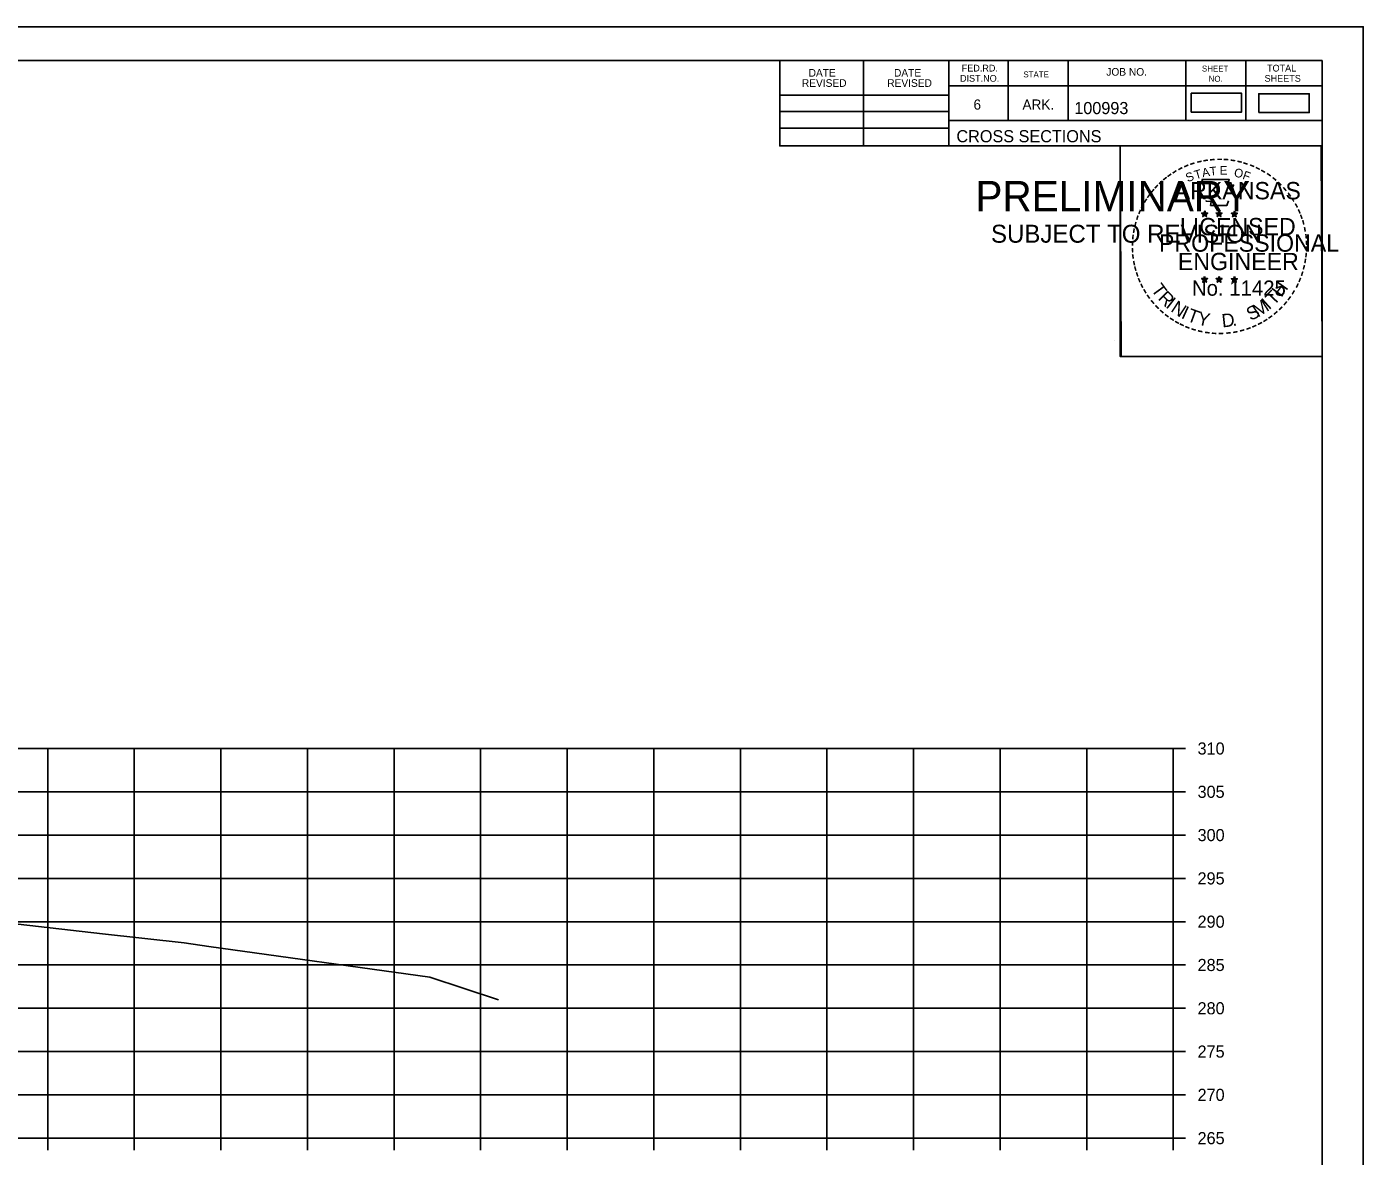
# Model space of a CAD drawing. Extents: x 4667 to 1632277, y -2100 to 724501.
# Drawn here: x 5814.8 to 5969.1, y 1319.2 to 1449.6 of the extents above; entities that cross this region are included whole.
import ezdxf

# ---------------------------------------------------------------- set-up
doc = ezdxf.new("R2010")
doc.units = 0
for name, color, linetype in [('Default', 7, 'Continuous'), ('R_Axis', 7, 'Continuous'), ('R_Axis Annot', 7, 'Continuous'), ('R_Border', 7, 'Continuous'), ('R_Border PE', 7, 'Continuous'), ('R_Border Prem', 7, 'Continuous'), ('R_Exist Surface', 7, 'Continuous'), ('R_Grid', 7, 'Continuous'), ('R_No Plot', 7, 'Continuous')]:
    doc.layers.add(name, color=color, linetype=linetype)

msp = doc.modelspace()

# ---------------------------------------------------------------- linework, layer by layer
at = {"layer": 'Default'}
for points in [[(5949.24, 1439.78), (5955.07, 1439.78), (5955.07, 1441.97), (5949.24, 1441.97)], [(5957.04, 1439.72), (5962.87, 1439.72), (5962.87, 1441.91), (5957.04, 1441.91)]]:
    msp.add_lwpolyline(points, close=True, dxfattribs=at)
at = {"layer": 'R_Axis'}
for p, q in [((5947.18, 1321.29), (5947.18, 1366.29)), ((5948.58, 1366.29), (5947.18, 1366.29)), ((5948.58, 1361.29), (5947.18, 1361.29)), ((5948.58, 1356.29), (5947.18, 1356.29)), ((5948.58, 1351.29), (5947.18, 1351.29)), ((5948.58, 1346.29), (5947.18, 1346.29)), ((5948.58, 1341.29), (5947.18, 1341.29)), ((5948.58, 1336.29), (5947.18, 1336.29)), ((5948.58, 1331.29), (5947.18, 1331.29)), ((5948.58, 1326.29), (5947.18, 1326.29)), ((5667.18, 1321.29), (5947.18, 1321.29)), ((5817.18, 1319.89), (5817.18, 1321.29)), ((5827.18, 1319.89), (5827.18, 1321.29)), ((5837.18, 1319.89), (5837.18, 1321.29)), ((5847.18, 1319.89), (5847.18, 1321.29)), ((5857.18, 1319.89), (5857.18, 1321.29)), ((5867.18, 1319.89), (5867.18, 1321.29)), ((5877.18, 1319.89), (5877.18, 1321.29)), ((5887.18, 1319.89), (5887.18, 1321.29)), ((5897.18, 1319.89), (5897.18, 1321.29)), ((5907.18, 1319.89), (5907.18, 1321.29)), ((5917.18, 1319.89), (5917.18, 1321.29)), ((5927.18, 1319.89), (5927.18, 1321.29)), ((5937.18, 1319.89), (5937.18, 1321.29)), ((5947.18, 1319.89), (5947.18, 1321.29)), ((5948.58, 1321.29), (5947.18, 1321.29))]:
    msp.add_line(p, q, dxfattribs=at)
at = {"layer": 'R_Border'}
for p, q in [((5648.18, 1445.75), (5964.36, 1445.75)), ((5901.72, 1435.87), (5901.72, 1445.75)), ((5911.4, 1435.87), (5911.4, 1445.75)), ((5921.26, 1445.75), (5921.26, 1435.87)), ((5928.1, 1445.75), (5928.1, 1438.81)), ((5935.04, 1445.75), (5935.04, 1438.81)), ((5948.62, 1445.75), (5948.62, 1438.81)), ((5955.56, 1445.75), (5955.56, 1438.81)), ((5964.36, 1240.29), (5964.36, 1445.75)), ((5964.36, 1442.81), (5921.26, 1442.81)), ((5964.36, 1442.83), (5964.36, 1442.83)), ((5901.72, 1441.73), (5921.26, 1441.73)), ((5901.72, 1439.87), (5921.26, 1439.87)), ((5964.36, 1438.81), (5921.26, 1438.81)), ((5924.22, 1438.81), (5964.36, 1438.81)), ((5901.72, 1437.93), (5921.26, 1437.93)), ((5964.36, 1435.87), (5901.72, 1435.87))]:
    msp.add_line(p, q, dxfattribs=at)
at = {"layer": 'R_Border PE'}
for p, q in [((5950.45, 1428.12), (5950.8, 1428.01)), ((5950.45, 1428.12), (5950.7, 1428.08)), ((5950.45, 1428.12), (5950.69, 1428)), ((5950.58, 1427.71), (5950.8, 1428.01)), ((5950.58, 1427.71), (5950.71, 1427.96)), ((5950.58, 1427.71), (5950.8, 1427.93)), ((5950.8, 1428.38), (5950.76, 1428.12)), ((5950.8, 1428.01), (5950.8, 1428.38)), ((5950.8, 1428.38), (5950.85, 1428.13)), ((5951.15, 1428.12), (5950.8, 1428.01)), ((5951.01, 1427.71), (5950.8, 1428.01)), ((5951.01, 1427.71), (5950.8, 1427.93)), ((5951.15, 1428.12), (5950.86, 1428.07)), ((5951.01, 1427.71), (5950.87, 1428.01)), ((5951.15, 1428.12), (5950.94, 1428.02)), ((5952.12, 1428.12), (5952.47, 1428.01)), ((5952.12, 1428.12), (5952.37, 1428.08)), ((5952.12, 1428.12), (5952.36, 1428)), ((5952.25, 1427.71), (5952.47, 1428.01)), ((5952.25, 1427.71), (5952.38, 1427.96)), ((5952.25, 1427.71), (5952.47, 1427.93)), ((5952.47, 1428.38), (5952.43, 1428.12)), ((5952.47, 1428.01), (5952.47, 1428.38)), ((5952.47, 1428.38), (5952.52, 1428.13)), ((5952.82, 1428.12), (5952.47, 1428.01)), ((5952.68, 1427.71), (5952.47, 1428.01)), ((5952.68, 1427.71), (5952.47, 1427.93)), ((5952.82, 1428.12), (5952.53, 1428.07)), ((5952.68, 1427.71), (5952.54, 1428.01)), ((5952.82, 1428.12), (5952.61, 1428.02)), ((5953.88, 1428.11), (5954.23, 1428)), ((5953.88, 1428.11), (5954.14, 1428.07)), ((5953.88, 1428.11), (5954.12, 1427.99)), ((5954.02, 1427.7), (5954.23, 1428)), ((5954.02, 1427.7), (5954.14, 1427.95)), ((5954.02, 1427.7), (5954.23, 1427.92)), ((5954.23, 1428.36), (5954.19, 1428.11)), ((5954.23, 1428), (5954.23, 1428.36)), ((5954.23, 1428.36), (5954.28, 1428.11)), ((5954.58, 1428.11), (5954.23, 1428)), ((5954.45, 1427.7), (5954.23, 1428)), ((5954.45, 1427.7), (5954.23, 1427.92)), ((5954.58, 1428.11), (5954.29, 1428.06)), ((5954.45, 1427.7), (5954.31, 1427.99)), ((5954.58, 1428.11), (5954.38, 1428.01)), ((5950.45, 1420.55), (5950.79, 1420.44)), ((5950.45, 1420.55), (5950.7, 1420.5)), ((5950.45, 1420.55), (5950.68, 1420.43)), ((5950.58, 1420.14), (5950.79, 1420.44)), ((5950.58, 1420.14), (5950.7, 1420.39)), ((5950.58, 1420.14), (5950.79, 1420.36)), ((5950.79, 1420.8), (5950.75, 1420.55)), ((5950.79, 1420.44), (5950.79, 1420.8)), ((5950.79, 1420.8), (5950.84, 1420.55)), ((5951.14, 1420.55), (5950.79, 1420.44)), ((5951.01, 1420.14), (5950.79, 1420.44)), ((5951.01, 1420.14), (5950.79, 1420.36)), ((5951.14, 1420.55), (5950.86, 1420.5)), ((5951.01, 1420.14), (5950.87, 1420.43)), ((5951.14, 1420.55), (5950.94, 1420.45)), ((5952.11, 1420.55), (5952.46, 1420.44)), ((5952.11, 1420.55), (5952.37, 1420.5)), ((5952.11, 1420.55), (5952.35, 1420.43)), ((5952.25, 1420.14), (5952.46, 1420.44)), ((5952.25, 1420.14), (5952.37, 1420.39)), ((5952.25, 1420.14), (5952.46, 1420.36)), ((5952.46, 1420.8), (5952.42, 1420.55)), ((5952.46, 1420.44), (5952.46, 1420.8)), ((5952.46, 1420.8), (5952.51, 1420.55)), ((5952.81, 1420.55), (5952.46, 1420.44)), ((5952.68, 1420.14), (5952.46, 1420.44)), ((5952.68, 1420.14), (5952.46, 1420.36)), ((5952.81, 1420.55), (5952.52, 1420.5)), ((5952.68, 1420.14), (5952.54, 1420.43)), ((5952.81, 1420.55), (5952.61, 1420.45)), ((5953.88, 1420.54), (5954.23, 1420.43)), ((5953.88, 1420.54), (5954.13, 1420.49)), ((5953.88, 1420.54), (5954.12, 1420.42)), ((5954.01, 1420.13), (5954.23, 1420.43)), ((5954.01, 1420.13), (5954.14, 1420.38)), ((5954.01, 1420.13), (5954.23, 1420.35)), ((5954.23, 1420.79), (5954.19, 1420.54)), ((5954.23, 1420.43), (5954.23, 1420.79)), ((5954.23, 1420.79), (5954.28, 1420.54)), ((5954.58, 1420.54), (5954.23, 1420.43)), ((5954.44, 1420.13), (5954.23, 1420.43)), ((5954.44, 1420.13), (5954.23, 1420.35)), ((5954.58, 1420.54), (5954.29, 1420.49)), ((5954.44, 1420.13), (5954.31, 1420.42)), ((5954.58, 1420.54), (5954.37, 1420.44))]:
    msp.add_line(p, q, dxfattribs=at)
for points in [[(5950.49, 1432), (5950.76, 1431.17)], [(5954, 1431.08), (5954.14, 1431.36), (5953.46, 1431.34), (5953.61, 1432), (5950.49, 1432)], [(5950.98, 1429.58), (5950.98, 1429.49), (5951.55, 1429.47), (5951.49, 1429), (5953.36, 1429), (5953.56, 1429.53)], [(5950.8, 1428.38), (5951.01, 1427.71), (5950.45, 1428.12), (5951.15, 1428.12), (5950.58, 1427.71), (5950.8, 1428.38)], [(5952.47, 1428.38), (5952.68, 1427.71), (5952.12, 1428.12), (5952.82, 1428.12), (5952.25, 1427.71), (5952.47, 1428.38)], [(5954.23, 1428.36), (5954.45, 1427.7), (5953.88, 1428.11), (5954.58, 1428.11), (5954.02, 1427.7), (5954.23, 1428.36)], [(5950.79, 1420.8), (5951.01, 1420.14), (5950.45, 1420.55), (5951.14, 1420.55), (5950.58, 1420.14), (5950.79, 1420.8)], [(5952.46, 1420.8), (5952.68, 1420.14), (5952.11, 1420.55), (5952.81, 1420.55), (5952.25, 1420.14), (5952.46, 1420.8)], [(5954.23, 1420.79), (5954.44, 1420.13), (5953.88, 1420.54), (5954.58, 1420.54), (5954.01, 1420.13), (5954.23, 1420.79)]]:
    msp.add_lwpolyline(points, dxfattribs=at)
for centre, radius in [((5950.8, 1428.01), 0.172), ((5950.8, 1428.01), 0.145), ((5950.8, 1428.01), 0.116), ((5950.8, 1428.01), 0.0991), ((5950.8, 1428.01), 0.0747), ((5950.8, 1428.01), 0.0495), ((5950.8, 1428.01), 0.0296), ((5952.47, 1428.01), 0.172), ((5952.47, 1428.01), 0.145), ((5952.47, 1428.01), 0.116), ((5952.47, 1428.01), 0.0991), ((5952.47, 1428.01), 0.0747), ((5952.47, 1428.01), 0.0495), ((5952.47, 1428.01), 0.0296), ((5954.23, 1428), 0.172), ((5954.23, 1428), 0.145), ((5954.23, 1428), 0.116), ((5954.23, 1428), 0.0991), ((5954.23, 1428), 0.0747), ((5954.23, 1428), 0.0495), ((5954.23, 1428), 0.0296), ((5950.79, 1420.44), 0.172), ((5950.79, 1420.44), 0.145), ((5950.79, 1420.44), 0.116), ((5950.79, 1420.44), 0.0991), ((5950.79, 1420.44), 0.0747), ((5950.79, 1420.44), 0.0495), ((5950.79, 1420.44), 0.0296), ((5952.46, 1420.44), 0.172), ((5952.46, 1420.44), 0.145), ((5952.46, 1420.44), 0.116), ((5952.46, 1420.44), 0.0991), ((5952.46, 1420.44), 0.0747), ((5952.46, 1420.44), 0.0495), ((5952.46, 1420.44), 0.0296), ((5954.23, 1420.43), 0.172), ((5954.23, 1420.43), 0.145), ((5954.23, 1420.43), 0.116), ((5954.23, 1420.43), 0.0991), ((5954.23, 1420.43), 0.0747), ((5954.23, 1420.43), 0.0495), ((5954.23, 1420.43), 0.0296)]:
    msp.add_circle(centre, radius, dxfattribs=at)
at = {"layer": 'R_Exist Surface'}
msp.add_lwpolyline([(5805, 1347.02), (5823.52, 1344.89), (5832.94, 1343.83), (5835.8, 1343.41), (5861.3, 1339.87), (5869.24, 1337.26)], dxfattribs=at)
at = {"layer": 'R_Grid'}
for p, q in [((5667.18, 1366.29), (5947.18, 1366.29)), ((5817.18, 1321.29), (5817.18, 1366.29)), ((5827.18, 1321.29), (5827.18, 1366.29)), ((5837.18, 1321.29), (5837.18, 1366.29)), ((5847.18, 1321.29), (5847.18, 1366.29)), ((5857.18, 1321.29), (5857.18, 1366.29)), ((5867.18, 1321.29), (5867.18, 1366.29)), ((5877.18, 1321.29), (5877.18, 1366.29)), ((5887.18, 1321.29), (5887.18, 1366.29)), ((5897.18, 1321.29), (5897.18, 1366.29)), ((5907.18, 1321.29), (5907.18, 1366.29)), ((5917.18, 1321.29), (5917.18, 1366.29)), ((5927.18, 1321.29), (5927.18, 1366.29)), ((5937.18, 1321.29), (5937.18, 1366.29)), ((5947.18, 1321.29), (5947.18, 1366.29)), ((5667.18, 1361.29), (5947.18, 1361.29)), ((5667.18, 1356.29), (5947.18, 1356.29)), ((5667.18, 1351.29), (5947.18, 1351.29)), ((5667.18, 1346.29), (5947.18, 1346.29)), ((5667.18, 1341.29), (5947.18, 1341.29)), ((5667.18, 1336.29), (5947.18, 1336.29)), ((5667.18, 1331.29), (5947.18, 1331.29)), ((5667.18, 1326.29), (5947.18, 1326.29)), ((5667.18, 1321.29), (5947.18, 1321.29))]:
    msp.add_line(p, q, dxfattribs=at)
at = {"layer": 'R_No Plot'}
for p, q in [((5635.78, 1449.64), (5969.12, 1449.64)), ((5940.4, 1413.41), (5940.4, 1413.41))]:
    msp.add_line(p, q, dxfattribs=at)
for points in [[(5635.78, 1449.64), (5969.12, 1449.64), (5969.12, 1236.3), (5635.78, 1236.3)], [(5882.1, 1445.75), (5901.72, 1445.75), (5901.72, 1435.87), (5917.84, 1435.87), (5941.04, 1435.87), (5941.04, 1411.54), (5964.36, 1411.54), (5964.36, 1240.29), (5648.18, 1240.29), (5648.18, 1445.75)], [(5941.04, 1435.87), (5964.24, 1435.87), (5964.36, 1411.54), (5941.16, 1411.54)]]:
    msp.add_lwpolyline(points, close=True, dxfattribs=at)

# ---------------------------------------------------------------- texts
at = {"layer": 'R_Axis Annot'}
for s, p in [('310', (5949.98, 1365.59)), ('305', (5949.98, 1360.59)), ('300', (5949.98, 1355.59)), ('295', (5949.98, 1350.59)), ('290', (5949.98, 1345.59)), ('285', (5949.98, 1340.59)), ('280', (5949.98, 1335.59)), ('275', (5949.98, 1330.59)), ('270', (5949.98, 1325.59)), ('265', (5949.98, 1320.59))]:
    msp.add_text(s, height=1.4, dxfattribs=at).set_placement(p)
at = {"layer": 'R_Border'}
for s, height, p in [('FED.RD.', 0.782, (5922.74, 1444.47)), ('JOB NO.', 0.879, (5939.44, 1443.99)), ('SHEET', 0.684, (5950.48, 1444.47)), ('TOTAL', 0.782, (5958, 1444.47)), ('REVISED', 0.879, (5904.28, 1442.7)), ('DATE', 0.879, (5905.06, 1443.88)), ('REVISED', 0.879, (5914.14, 1442.7)), ('DATE', 0.879, (5914.92, 1443.88)), ('DIST.NO.', 0.782, (5922.54, 1443.29)), ('STATE', 0.684, (5929.86, 1443.79)), ('NO.', 0.684, (5951.26, 1443.29)), ('SHEETS', 0.782, (5957.72, 1443.29)), ('6', 1.17, (5924.1, 1440.07)), ('ARK.', 1.172, (5929.76, 1440.07)), ('100993', 1.4, (5935.74, 1439.55)), ('CROSS SECTIONS', 1.4, (5922.13, 1436.3))]:
    msp.add_text(s, height=height, rotation=360, dxfattribs=at).set_placement(p)
at = {"layer": 'R_Border PE'}
for s, height, rotation, p in [('-', 1.6, 13.6301, (5949.99, 1433.37)), ('-', 1.6, 10.2193, (5950.67, 1433.53)), ('-', 1.6, 5.8968, (5951.39, 1433.64)), ('-', 1.6, 0.1862, (5952.17, 1433.71)), ('-', 1.6, 357.743, (5952.89, 1433.7)), ('-', 1.6, 352.1617, (5953.63, 1433.64)), ('-', 1.6, 347.2049, (5954.35, 1433.53)), ('-', 1.6, 36.2317, (5946.8, 1431.78)), ('-', 1.6, 34.0636, (5947.37, 1432.17)), ('-', 1.6, 28.7918, (5947.97, 1432.54)), ('-', 1.6, 24.3072, (5948.6, 1432.86)), ('S', 1, 21.594, (5948.84, 1431.68)), ('-', 1.6, 19.1761, (5949.24, 1433.13)), ('T', 1, 16.4036, (5949.76, 1432.01)), ('A', 1, 11.2132, (5950.58, 1432.26)), ('T', 1, 6.0228, (5951.43, 1432.43)), ('E', 1, 0.8323, (5952.54, 1432.54)), ('O', 1, 350.4515, (5954.14, 1432.33)), ('F', 1, 340.0707, (5955.1, 1432.1)), ('-', 1.6, 342.3362, (5954.99, 1433.37)), ('-', 1.6, 337.8551, (5955.72, 1433.15)), ('-', 1.6, 334.1211, (5956.35, 1432.88)), ('-', 1.6, 329.6409, (5956.93, 1432.6)), ('-', 1.6, 325.8627, (5957.58, 1432.24)), ('-', 1.6, 50.6142, (5945.04, 1430.02)), ('-', 1.6, 48.423, (5945.44, 1430.5)), ('-', 1.6, 42.9622, (5945.89, 1430.98)), ('-', 1.6, 38.9507, (5946.32, 1431.4)), ('ARKANSAS', 2, 360, (5947.34, 1429.71)), ('-', 1.6, 320.5297, (5958.19, 1431.81)), ('-', 1.6, 315.5786, (5958.78, 1431.32)), ('-', 1.6, 309.8797, (5959.35, 1430.77)), ('-', 1.6, 58.0706, (5944.3, 1428.92)), ('-', 1.6, 54.2325, (5944.62, 1429.45)), ('-', 1.6, 306.6522, (5959.88, 1430.17)), ('-', 1.4, 303.6753, (5960.36, 1429.6)), ('-', 1.6, 72.3945, (5943.51, 1427.07)), ('-', 1.6, 67.7743, (5943.73, 1427.7)), ('-', 1.6, 62.8713, (5943.98, 1428.31)), ('DWB', 0.01, 360, (5950.79, 1428.01)), ('DWB', 0.01, 360, (5952.46, 1428.01)), ('DWB', 0.01, 360, (5954.22, 1428)), ('-', 1.6, 299.6684, (5960.68, 1429)), ('-', 1.6, 294.6628, (5961.01, 1428.38)), ('-', 1.6, 290.5728, (5961.26, 1427.81)), ('-', 1.6, 81.2013, (5943.18, 1425.64)), ('-', 1.6, 75.461, (5943.31, 1426.35)), ('LICENSED', 2, 360, (5947.94, 1425.56)), ('-', 1.6, 285.1233, (5961.5, 1427.23)), ('-', 1.6, 280.5493, (5961.7, 1426.48)), ('-', 1.6, 89.0622, (5943.08, 1424.25)), ('-', 1.6, 85.1863, (5943.1, 1424.95)), ('PROFESSIONAL', 2, 360, (5945.52, 1423.66)), ('-', 1.6, 276.5962, (5961.86, 1425.72)), ('-', 1.6, 274.3301, (5961.92, 1424.99)), ('-', 1.6, 94.1959, (5943.11, 1423.52)), ('-', 1.6, 98.9479, (5943.18, 1422.86)), ('ENGINEER', 2, 360, (5947.7, 1421.53)), ('-', 1.6, 263.5172, (5961.94, 1423.7)), ('-', 1.6, 269.9407, (5961.95, 1424.36)), ('-', 1.6, 101.7149, (5943.32, 1422.12)), ('-', 1.6, 105.4578, (5943.48, 1421.53)), ('-', 1.6, 255.7626, (5961.75, 1422.36)), ('-', 1.6, 260.9953, (5961.86, 1423.04)), ('-', 1.6, 109.0874, (5943.7, 1420.9)), ('-', 1.6, 114.0643, (5943.95, 1420.3)), ('T', 1.54, 306.0406, (5944.55, 1419.28)), ('No. 11425', 1.757, 360, (5949.33, 1418.58)), ('DWB', 0.01, 360, (5950.78, 1420.43)), ('DWB', 0.01, 360, (5952.45, 1420.43)), ('DWB', 0.01, 360, (5954.22, 1420.42)), ('H', 1.54, 54.6088, (5959.67, 1418.31)), ('-', 1.6, 247.8887, (5961.35, 1420.97)), ('-', 1.6, 252.8681, (5961.57, 1421.64)), ('-', 1.6, 115.7289, (5944.25, 1419.68)), ('-', 1.6, 120.4471, (5944.61, 1419.1)), ('-', 1.6, 125.8934, (5945.01, 1418.54)), ('R', 1.54, 314.005, (5945.32, 1418.23)), ('T', 1.54, 46.6444, (5958.78, 1417.37)), ('-', 1.6, 239.0712, (5960.69, 1419.59)), ('-', 1.6, 244.6197, (5961.09, 1420.34)), ('-', 1.6, 130.7181, (5945.48, 1417.99)), ('-', 1.6, 134.2238, (5945.99, 1417.44)), ('I', 1.54, 321.9694, (5946.22, 1417.3)), ('N', 1.54, 326.5002, (5946.78, 1416.83)), ('I', 1.54, 335.3603, (5947.99, 1416.04)), ('T', 1.54, 339.8912, (5948.65, 1415.71)), ('S', 1.54, 26.9312, (5956.1, 1415.64)), ('M', 1.54, 32.6563, (5956.94, 1416.04)), ('I', 1.54, 42.1136, (5958.22, 1416.89)), ('-', 1.6, 225.7653, (5959.38, 1417.81)), ('-', 1.6, 231.2538, (5959.86, 1418.37)), ('-', 1.6, 233.8452, (5960.29, 1418.94)), ('-', 1.6, 138.9338, (5946.52, 1416.98)), ('-', 1.6, 144.6463, (5947.07, 1416.57)), ('-', 1.6, 148.0898, (5947.64, 1416.2)), ('-', 1.6, 151.5704, (5948.21, 1415.87)), ('Y', 1.54, 347.8556, (5949.87, 1415.27)), ('D', 1.54, 6.3969, (5952.85, 1414.91)), ('-', 1.6, 207.3568, (5957.22, 1416.09)), ('-', 1.6, 212.2491, (5957.78, 1416.44)), ('-', 1.6, 215.7363, (5958.31, 1416.83)), ('-', 1.6, 221.0851, (5958.86, 1417.3)), ('-', 1.6, 154.6002, (5948.74, 1415.63)), ('-', 1.6, 158.5612, (5949.36, 1415.37)), ('-', 1.6, 162.7983, (5950.05, 1415.16)), ('-', 1.6, 167.5555, (5950.76, 1415)), ('-', 1.6, 173.1155, (5951.53, 1414.89)), ('-', 1.6, 176.5183, (5952.28, 1414.83)), ('-', 1.6, 181.5918, (5953.03, 1414.85)), ('-', 1.6, 185.8167, (5953.84, 1414.93)), ('-', 1.6, 191.2858, (5954.57, 1415.06)), ('.', 1.54, 13.7642, (5954.05, 1415.04)), ('-', 1.6, 195.4743, (5955.3, 1415.26)), ('-', 1.6, 200.7184, (5955.98, 1415.5)), ('-', 1.6, 204.2516, (5956.6, 1415.77))]:
    msp.add_text(s, height=height, rotation=rotation, dxfattribs=at).set_placement(p)
at = {"layer": 'R_Border Prem'}
for s, height, p in [('PRELIMINARY', 3.5, (5924.32, 1428.33)), ('DWB', 0.01, (5925.06, 1430.18)), ('SUBJECT TO REVISION', 2.0751, (5926.12, 1424.7))]:
    msp.add_text(s, height=height, rotation=360, dxfattribs=at).set_placement(p)

doc.saveas('drawing.dxf')
